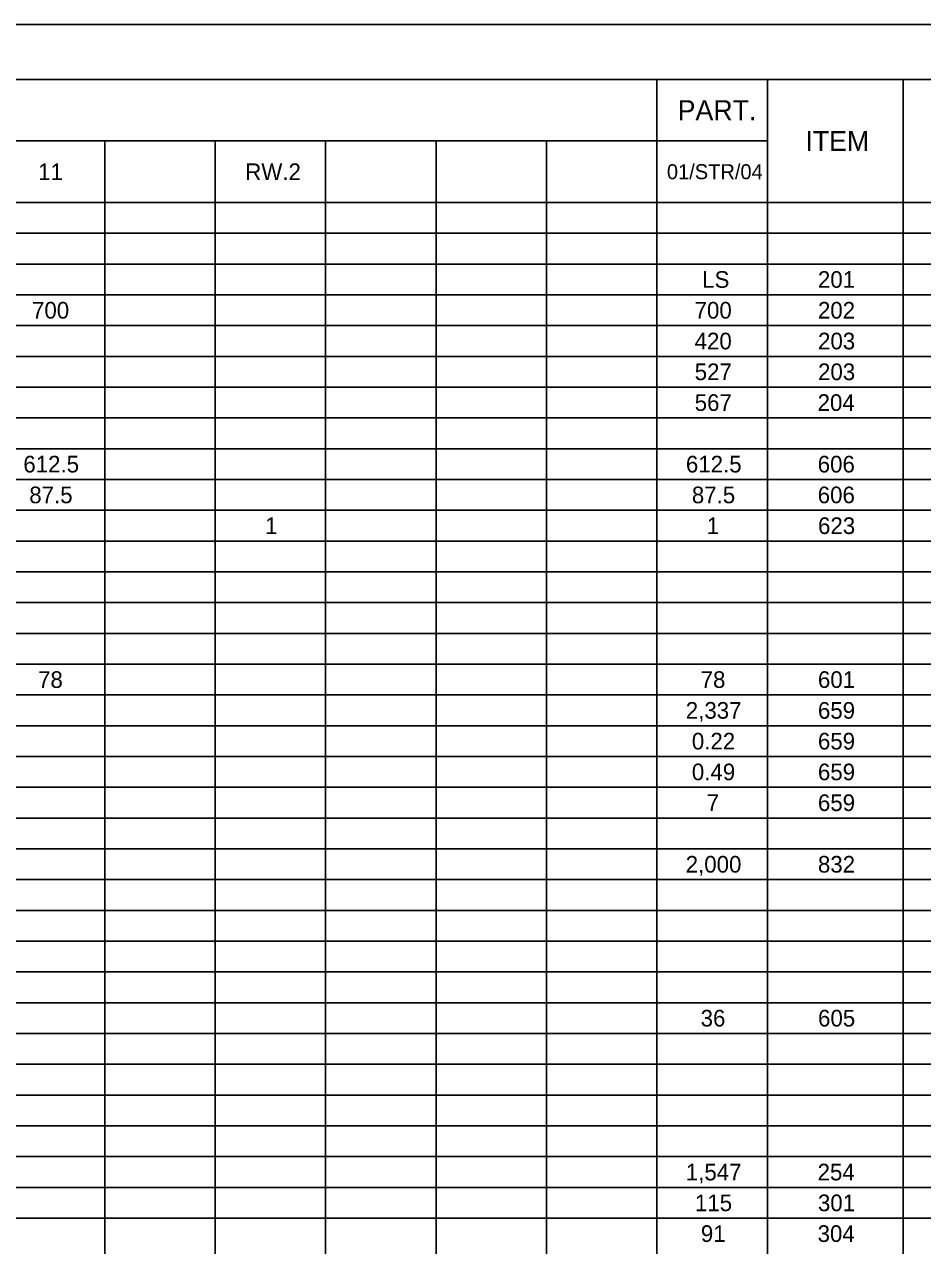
# Model space of a CAD drawing. Extents: x 0 to 34, y 0 to 22.
# Drawn here: x 8.81 to 16.98, y 10.89 to 22 of the extents above; entities that cross this region are included whole.
import ezdxf

# ---------------------------------------------------------------- set-up
doc = ezdxf.new("R2010")
doc.units = 0
for name, color, linetype in [('Default', 7, 'Continuous'), ('SH_Border', 7, 'Continuous'), ('SH_Cut_Line', 7, 'Continuous')]:
    doc.layers.add(name, color=color, linetype=linetype)

msp = doc.modelspace()

# ---------------------------------------------------------------- linework, layer by layer
at = {"layer": 'Default'}
for p, q in [((1.5, 21.5), (32.004, 21.5)), ((14.561, 21.5), (14.561, 0.5)), ((15.566, 21.5), (15.566, 0.5)), ((16.801, 21.5), (16.801, 0.5)), ((1.5, 20.94), (15.566, 20.94)), ((9.538, 20.94), (9.538, 0.5)), ((10.542, 20.94), (10.542, 0.5)), ((11.547, 20.94), (11.547, 0.5)), ((12.552, 20.94), (12.552, 0.5)), ((13.556, 20.94), (13.556, 0.5)), ((1.5, 20.38), (32.004, 20.38)), ((1.5, 20.1), (32.004, 20.1)), ((1.5, 19.82), (32.004, 19.82)), ((1.5, 19.54), (32.004, 19.54)), ((1.5, 19.26), (32.004, 19.26)), ((1.5, 18.98), (32.004, 18.98)), ((1.5, 18.7), (32.004, 18.7)), ((1.5, 18.42), (32.004, 18.42)), ((1.5, 18.14), (32.004, 18.14)), ((1.5, 17.86), (32.004, 17.86)), ((1.5, 17.58), (32.004, 17.58)), ((1.5, 17.3), (32.004, 17.3)), ((1.5, 17.02), (32.004, 17.02)), ((1.5, 16.74), (32.004, 16.74)), ((1.5, 16.46), (32.004, 16.46)), ((1.5, 16.18), (32.004, 16.18)), ((1.5, 15.9), (32.004, 15.9)), ((1.5, 15.62), (32.004, 15.62)), ((1.5, 15.34), (32.004, 15.34)), ((1.5, 15.06), (32.004, 15.06)), ((1.5, 14.78), (32.004, 14.78)), ((1.5, 14.5), (32.004, 14.5)), ((1.5, 14.22), (32.004, 14.22)), ((1.5, 13.94), (32.004, 13.94)), ((1.5, 13.66), (32.004, 13.66)), ((1.5, 13.38), (32.004, 13.38)), ((1.5, 13.1), (32.004, 13.1)), ((1.5, 12.82), (32.004, 12.82)), ((1.5, 12.54), (32.004, 12.54)), ((1.5, 12.26), (32.004, 12.26)), ((1.5, 11.98), (32.004, 11.98)), ((1.5, 11.7), (32.004, 11.7)), ((1.5, 11.42), (32.004, 11.42)), ((1.5, 11.14), (32.004, 11.14))]:
    msp.add_line(p, q, dxfattribs=at)
at = {"layer": 'SH_Border'}
msp.add_lwpolyline([(1.5, 21.5), (33.5, 21.5), (33.5, 0.5), (1.5, 0.5)], close=True, dxfattribs=at)
at = {"layer": 'SH_Cut_Line'}
msp.add_lwpolyline([(0, 0), (34, 0), (34, 22), (0, 22)], close=True, dxfattribs=at)

# ---------------------------------------------------------------- texts
at = {"layer": 'Default'}
for s, height, p in [('PART.', 0.1818, (14.75, 21.129)), ('ITEM', 0.1818, (15.912, 20.849)), ('11', 0.1515, (8.932, 20.584)), ('RW.2', 0.1515, (10.816, 20.584)), ('01/STR/04', 0.1364, (14.652, 20.592)), ('LS', 0.1515, (14.973, 19.604)), ('201', 0.1515, (16.026, 19.604)), ('700', 0.1515, (8.876, 19.324)), ('700', 0.1515, (14.904, 19.324)), ('202', 0.1515, (16.026, 19.324)), ('420', 0.1515, (14.904, 19.044)), ('203', 0.1515, (16.027, 19.044)), ('527', 0.1515, (14.905, 18.764)), ('203', 0.1515, (16.027, 18.764)), ('567', 0.1515, (14.905, 18.484)), ('204', 0.1515, (16.023, 18.484)), ('612.5', 0.1515, (8.797, 17.924)), ('612.5', 0.1515, (14.825, 17.924)), ('606', 0.1515, (16.024, 17.924)), ('87.5', 0.1515, (8.851, 17.644)), ('87.5', 0.1515, (14.879, 17.644)), ('606', 0.1515, (16.024, 17.644)), ('1', 0.152, (10.996, 17.364)), ('1', 0.152, (15.015, 17.364)), ('623', 0.1515, (16.027, 17.364)), ('78', 0.1515, (8.931, 15.964)), ('78', 0.1515, (14.959, 15.964)), ('601', 0.1515, (16.026, 15.964)), ('2,337', 0.1515, (14.824, 15.684)), ('659', 0.1515, (16.026, 15.684)), ('0.22', 0.1515, (14.879, 15.404)), ('659', 0.1515, (16.026, 15.404)), ('0.49', 0.1515, (14.879, 15.124)), ('659', 0.1515, (16.026, 15.124)), ('659', 0.1515, (16.026, 14.844)), ('7', 0.152, (15.014, 14.844)), ('2,000', 0.1515, (14.823, 14.284)), ('832', 0.1515, (16.026, 14.284)), ('36', 0.1515, (14.959, 12.884)), ('605', 0.1515, (16.027, 12.884)), ('1,547', 0.1515, (14.824, 11.484)), ('254', 0.1515, (16.023, 11.484)), ('115', 0.1515, (14.907, 11.204)), ('301', 0.1515, (16.026, 11.204)), ('91', 0.1515, (14.961, 10.924)), ('304', 0.1515, (16.023, 10.924))]:
    msp.add_text(s, height=height, dxfattribs=at).set_placement(p)

doc.saveas('drawing.dxf')
